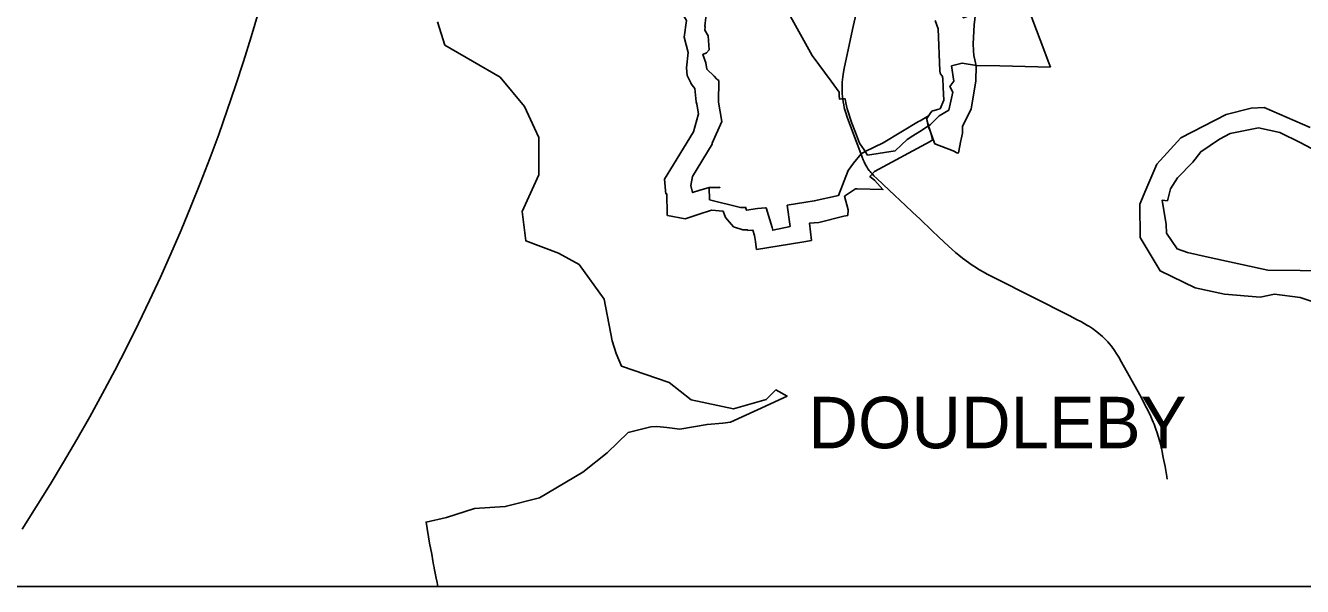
# Model space of a CAD drawing. Extents: x -759276 to -751881, y -1176141 to -1171097.
# Drawn here: x -757836 to -754995, y -1176141 to -1174894 of the extents above; entities that cross this region are included whole.
import ezdxf

# ---------------------------------------------------------------- set-up
doc = ezdxf.new("R2010")
doc.units = 0
for name, color, linetype in [('A_HRU', 7, 'Continuous'), ('A_OBCE', 7, 'Continuous'), ('A_SILNICE', 7, 'Continuous'), ('A_USES', 7, 'Continuous'), ('AA_vyrezy', 7, 'Continuous')]:
    doc.layers.add(name, color=color, linetype=linetype)

msp = doc.modelspace()

# ---------------------------------------------------------------- linework, layer by layer
at = {"layer": 'A_HRU'}
for points in [[(-759275.6, -1176140.6), (-759275.6, -1171097.2), (-751880.9, -1171097.2), (-751880.9, -1176140.6)], [(-751880.9, -1172828.3), (-753894.3, -1172828.3), (-753894.3, -1171097.2), (-759275.6, -1171097.2), (-759275.6, -1176140.6), (-753894.3, -1176140.6), (-753894.3, -1174884.8), (-751880.9, -1174884.8)]]:
    msp.add_lwpolyline(points, close=True, dxfattribs=at)
at = {"layer": 'A_OBCE'}
for p, q in [((-756085.5, -1174960.4), (-756144.8, -1174853.9)), ((-756919.6, -1174885.6), (-756903.2, -1174937.1)), ((-756903.2, -1174937.1), (-756780.2, -1175008.1)), ((-755667.9, -1174983.4), (-755555.2, -1174986)), ((-755556.7, -1174982.2), (-755555.2, -1174986)), ((-756780.2, -1175008.1), (-756726, -1175073.4)), ((-755781.7, -1175081.8), (-755772.9, -1175041.9)), ((-755772.9, -1175041.9), (-755781.7, -1175081.8)), ((-756014.6, -1175056.5), (-756020.6, -1175056.9)), ((-755802.9, -1175094.6), (-755817.8, -1175108.9)), ((-755781.7, -1175081.8), (-755802.9, -1175094.6)), ((-756693.9, -1175142.4), (-756703.6, -1175121.8)), ((-755989.3, -1175131.2), (-755997.3, -1175110.6)), ((-755989.3, -1175131.2), (-755980, -1175155.2)), ((-755825.3, -1175116.2), (-755826.5, -1175116.9)), ((-756694.1, -1175225.4), (-756693.9, -1175142.4)), ((-755980, -1175155.2), (-755970.2, -1175170.3)), ((-755874.6, -1175147.3), (-755901.1, -1175171.9)), ((-755861.7, -1175139.2), (-755874.6, -1175147.3)), ((-755962.6, -1175182.1), (-755967.9, -1175173.9)), ((-755901.1, -1175171.9), (-755962.6, -1175182.1)), ((-756548.7, -1175502.1), (-756530.6, -1175594.2)), ((-756530.6, -1175594.2), (-756521.6, -1175622.6)), ((-756188.2, -1175724.7), (-756260.6, -1175746)), ((-756166.5, -1175703.8), (-756188.2, -1175724.7)), ((-756267.7, -1175775.6), (-756207, -1175747.8)), ((-756284.1, -1175777.3), (-756319.6, -1175780.2)), ((-756284.1, -1175777.3), (-756267.7, -1175775.6)), ((-756541.7, -1175843.4), (-756495.4, -1175798)), ((-756495.4, -1175798), (-756541.7, -1175843.4)), ((-756541.7, -1175843.4), (-756595.6, -1175886.8)), ((-756595.6, -1175886.8), (-756692.4, -1175943.3)), ((-756692.4, -1175943.3), (-756768.6, -1175962.9)), ((-756944.6, -1175997.5), (-756936.9, -1176044.7)), ((-756936.9, -1176044.7), (-756932.2, -1176068.8)), ((-756926.5, -1176100.1), (-756922.1, -1176121.9)), ((-756922.1, -1176121.9), (-756920, -1176131.7)), ((-756918.3, -1176140.6), (-756920, -1176131.7)), ((-756920, -1176131.7), (-756918.3, -1176140.6)), ((-756918.3, -1176140.6), (-754601.6, -1176140.6))]:
    msp.add_line(p, q, dxfattribs=at)
for points in [[(-759275.6, -1171919), (-759275.6, -1176140.6), (-756918.3, -1176140.6)], [(-755555.2, -1174986), (-755556.7, -1174982.2), (-755558.8, -1174976.6), (-755578.4, -1174925.4), (-755594.5, -1174882.4), (-755599.2, -1174869.9), (-755609.7, -1174845)], [(-756144.8, -1174853.9), (-756085.5, -1174960.4), (-756043.4, -1175017.2)], [(-755599.2, -1174869.9), (-755594.5, -1174882.4), (-755578.4, -1174925.4)], [(-756780.2, -1175008.1), (-756903.2, -1174937.1), (-756919.6, -1174885.6)], [(-755578.4, -1174925.4), (-755558.8, -1174976.6), (-755556.7, -1174982.2)], [(-756025.2, -1175049.4), (-756025.4, -1175041.5), (-756043.4, -1175017.2), (-756085.5, -1174960.4)], [(-755770.2, -1175017.4), (-755775.6, -1174983.5), (-755752, -1174977), (-755720, -1174982.3), (-755667.9, -1174983.4)], [(-755720, -1174982.3), (-755752, -1174977), (-755775.6, -1174983.5), (-755770.2, -1175017.4)], [(-755555.2, -1174986), (-755667.9, -1174983.4), (-755720, -1174982.3)], [(-756703.6, -1175121.8), (-756726, -1175073.4), (-756780.2, -1175008.1)], [(-756043.4, -1175017.2), (-756025.4, -1175041.5), (-756025.2, -1175049.4), (-756025, -1175057.1)], [(-755772.9, -1175041.9), (-755779.2, -1175029.3), (-755770.2, -1175017.4)], [(-755770.2, -1175017.4), (-755779.2, -1175029.3), (-755772.9, -1175041.9)], [(-756726, -1175073.4), (-756703.6, -1175121.8), (-756693.9, -1175142.4)], [(-756020.6, -1175056.9), (-756025, -1175057.1), (-756025.2, -1175049.4)], [(-756025, -1175057.1), (-756020.6, -1175056.9), (-756014.6, -1175056.5), (-756012.4, -1175056.4), (-756010.5, -1175065.4)], [(-756010.5, -1175065.4), (-756012.4, -1175056.4), (-756014.6, -1175056.5)], [(-756010.5, -1175065.4), (-756007.4, -1175079.1), (-755997.3, -1175110.6), (-755989.3, -1175131.2)], [(-755997.3, -1175110.6), (-756007.4, -1175079.1), (-756010.5, -1175065.4)], [(-755817.8, -1175108.9), (-755802.9, -1175094.6), (-755781.7, -1175081.8)], [(-755967.9, -1175173.9), (-755970.2, -1175170.3), (-755980, -1175155.2), (-755989.3, -1175131.2)], [(-755962.6, -1175182.1), (-755901.1, -1175171.9), (-755874.6, -1175147.3), (-755861.7, -1175139.2), (-755845.7, -1175129.1), (-755826.5, -1175116.9), (-755825.3, -1175116.2), (-755822.4, -1175113.4), (-755817.8, -1175108.9)], [(-755826.5, -1175116.9), (-755845.7, -1175129.1), (-755861.7, -1175139.2)], [(-755817.8, -1175108.9), (-755822.4, -1175113.4), (-755825.3, -1175116.2)], [(-756693.9, -1175142.4), (-756694.1, -1175225.4), (-756731.1, -1175307), (-756722.7, -1175372.6), (-756650.1, -1175399.8)], [(-755970.2, -1175170.3), (-755967.9, -1175173.9), (-755962.6, -1175182.1)], [(-756650.1, -1175399.8), (-756722.7, -1175372.6), (-756731.1, -1175307), (-756694.1, -1175225.4)], [(-756548.7, -1175502.1), (-756603.8, -1175425.2), (-756650.1, -1175399.8)], [(-756650.1, -1175399.8), (-756603.8, -1175425.2), (-756548.7, -1175502.1)], [(-756403.8, -1175687.1), (-756510, -1175651.2), (-756521.6, -1175622.6), (-756530.6, -1175594.2), (-756548.7, -1175502.1)], [(-756521.6, -1175622.6), (-756510, -1175651.2), (-756403.8, -1175687.1), (-756354.8, -1175726)], [(-756260.6, -1175746), (-756354.8, -1175726), (-756403.8, -1175687.1)], [(-756354.8, -1175726), (-756260.6, -1175746), (-756188.2, -1175724.7)], [(-756188.2, -1175724.7), (-756166.5, -1175703.8), (-756141.5, -1175717.5), (-756207, -1175747.8), (-756267.7, -1175775.6), (-756284.1, -1175777.3)], [(-756207, -1175747.8), (-756141.5, -1175717.5), (-756166.5, -1175703.8)], [(-756319.6, -1175780.2), (-756380.4, -1175790.9), (-756409.2, -1175787.6), (-756431.6, -1175785)], [(-756409.2, -1175787.6), (-756380.4, -1175790.9), (-756319.6, -1175780.2), (-756284.1, -1175777.3)], [(-756495.4, -1175798), (-756444.5, -1175786), (-756431.6, -1175785), (-756409.2, -1175787.6)], [(-756431.6, -1175785), (-756444.5, -1175786), (-756495.4, -1175798)], [(-756692.4, -1175943.3), (-756595.6, -1175886.8), (-756541.7, -1175843.4)], [(-756927, -1176098.3), (-756928, -1176092.5), (-756929.4, -1176083.8), (-756932.2, -1176068.8), (-756936.9, -1176044.7), (-756944.6, -1175997.5), (-756899.2, -1175987.1), (-756837.2, -1175967), (-756768.6, -1175962.9), (-756692.4, -1175943.3)], [(-756768.6, -1175962.9), (-756837.2, -1175967), (-756899.2, -1175987.1), (-756944.6, -1175997.5)], [(-756932.2, -1176068.8), (-756929.4, -1176083.8), (-756928, -1176092.5)], [(-756928, -1176092.5), (-756927, -1176098.3), (-756926.5, -1176100.1)], [(-756920, -1176131.7), (-756922.1, -1176121.9), (-756926.5, -1176100.1), (-756927, -1176098.3)]]:
    msp.add_lwpolyline(points, dxfattribs=at)
at = {"layer": 'A_SILNICE'}
for points in [[(-757317.7, -1174864.2), (-757333.9, -1174919), (-757350.9, -1174973.5), (-757368.6, -1175027.9), (-757387.1, -1175081.9), (-757406.2, -1175135.8), (-757426.1, -1175189.3), (-757446.7, -1175242.6), (-757468, -1175295.7), (-757490, -1175348.4), (-757512.6, -1175400.9), (-757536, -1175453), (-757560.1, -1175504.8), (-757584.9, -1175556.3), (-757610.9, -1175608.6), (-757637.6, -1175660.5), (-757665, -1175712), (-757693.1, -1175763.2), (-757721.9, -1175813.9), (-757751.3, -1175864.3), (-757781.5, -1175914.3), (-757812.3, -1175963.8), (-757843.8, -1176013)], [(-755295.7, -1175901.8), (-755296.7, -1175895.9), (-755300.2, -1175873.8), (-755304.3, -1175853.7), (-755307.6, -1175837.1), (-755309.8, -1175827.8), (-755312.1, -1175819.1), (-755315, -1175808.6), (-755316.3, -1175804.2), (-755318, -1175799.1), (-755320.8, -1175791.2), (-755324.7, -1175780), (-755326.7, -1175775.1), (-755329, -1175770), (-755332.3, -1175762.6), (-755335.9, -1175754.7), (-755341.5, -1175743.4), (-755356.8, -1175714.9), (-755397, -1175642.1), (-755403.3, -1175631.1), (-755409.2, -1175621.7), (-755413.1, -1175616), (-755419.8, -1175606.7), (-755424.7, -1175600.6), (-755427.9, -1175597), (-755431.2, -1175593.4), (-755436.4, -1175588.2), (-755439.6, -1175585.2), (-755444.1, -1175581.2), (-755447.9, -1175577.9), (-755452.1, -1175574.6), (-755462.1, -1175567.5), (-755468.6, -1175562.9), (-755474.4, -1175559.4), (-755480.4, -1175555.8), (-755486.6, -1175552.5), (-755497.1, -1175546.8), (-755512.5, -1175538.9), (-755678.7, -1175455.6), (-755696.3, -1175446.5), (-755705.3, -1175441.4), (-755714.5, -1175436.1), (-755722.4, -1175431), (-755729.9, -1175426.1), (-755751, -1175410.9), (-755759.1, -1175404.4), (-755766.5, -1175398.2), (-755782.3, -1175384.1), (-755804, -1175363.8), (-755819.3, -1175349), (-755845.4, -1175324.3), (-755862.5, -1175308.4), (-755878.1, -1175293.5), (-755914.5, -1175259.3), (-755941.4, -1175234), (-755948.1, -1175227.7), (-755951.7, -1175224), (-755955.1, -1175220.2), (-755956.7, -1175218.4), (-755958.6, -1175216.1), (-755961.6, -1175212), (-755964.2, -1175207.8), (-755966.6, -1175203.6), (-755970.2, -1175196.7), (-755972.4, -1175191.9), (-755974.5, -1175186.4), (-755977.7, -1175178.1), (-755993.7, -1175135.5), (-756007.8, -1175097.2), (-756010.9, -1175087.7), (-756012.7, -1175081.3), (-756014.1, -1175076), (-756015.5, -1175069.8), (-756016.7, -1175063.3), (-756017.5, -1175057.4), (-756018.2, -1175051.2), (-756018.6, -1175045.6), (-756019, -1175039.8), (-756019.1, -1175031.4), (-756018.6, -1175019.7), (-756017.5, -1175007.7), (-756015.9, -1174997), (-756014.4, -1174989.1), (-756005, -1174943.9), (-755994.2, -1174896.1), (-755987.8, -1174867)]]:
    msp.add_lwpolyline(points, dxfattribs=at)
at = {"layer": 'A_USES'}
for p, q in [((-755800.5, -1174999.8), (-755800.1, -1175000.7)), ((-755731.9, -1175078.6), (-755721.7, -1175017.1)), ((-755831.2, -1175099.4), (-755827, -1175094.1)), ((-755829.5, -1175106.2), (-755831.2, -1175099.4)), ((-755826, -1175093.6), (-755830.5, -1175100.2)), ((-755830.5, -1175100.2), (-755829.5, -1175106.2)), ((-755823.3, -1175089.4), (-755826, -1175093.6)), ((-755822.7, -1175129.8), (-755816.2, -1175146.7)), ((-755754, -1175146.1), (-755751.4, -1175132.7)), ((-756414, -1175235.4), (-756411.5, -1175268.3)), ((-756099.4, -1175286.1), (-756141.5, -1175293.2)), ((-756408.2, -1175312.1), (-756408, -1175314.6)), ((-756408, -1175314.6), (-756407.2, -1175316)), ((-756209.4, -1175391.3), (-756108.6, -1175375.2)), ((-756108.6, -1175375.2), (-756087.2, -1175371.8))]:
    msp.add_line(p, q, dxfattribs=at)
for points in [[(-755727.5, -1174934.6), (-755725.3, -1174892), (-755722, -1174866.9), (-755749.5, -1174876.3), (-755760.7, -1174830.8), (-755766, -1174805.8), (-755750.7, -1174799.5)], [(-756371.8, -1174871.2), (-756365.2, -1174882.7), (-756370.3, -1174919.2)], [(-756323.8, -1174896.4), (-756324.6, -1174895.3), (-756322, -1174876.1), (-756320.1, -1174862.4), (-756319.8, -1174859.7)], [(-756321, -1174954.5), (-756315.2, -1174948), (-756317, -1174916.6), (-756324.8, -1174903.7), (-756323.8, -1174896.4)], [(-755812.2, -1174882.8), (-755805.6, -1174900.8), (-755801.3, -1174994), (-755800.5, -1174999.8)], [(-756370.3, -1174919.2), (-756361.9, -1174953.7), (-756365.5, -1174987.6), (-756363.7, -1175004.4)], [(-756322.1, -1174976.4), (-756329.2, -1174958), (-756321, -1174954.5)], [(-755725.5, -1174962.7), (-755725.6, -1174962.1), (-755727.6, -1174935.3), (-755727.5, -1174934.6)], [(-756303.8, -1175006), (-756320.2, -1174990.5), (-756322.1, -1174976.4)], [(-755721.9, -1174976.2), (-755725.5, -1174963), (-755725.5, -1174962.7)], [(-755721.7, -1175017.1), (-755720.7, -1174982.8), (-755721.9, -1174976.2)], [(-756363.7, -1175004.4), (-756355.6, -1175020.7), (-756355.7, -1175021.4)], [(-756307.9, -1175157.2), (-756308.2, -1175155.2), (-756286.7, -1175106.7), (-756294.2, -1175063.9), (-756293.3, -1175016), (-756294.6, -1175014.8)], [(-756294.6, -1175014.8), (-756298.6, -1175011.8), (-756303.8, -1175006)], [(-755795.6, -1175009.3), (-755795.1, -1175010.3), (-755794.2, -1175031.7), (-755792.6, -1175059.3), (-755800.9, -1175078.8), (-755806.5, -1175080.3)], [(-755800.1, -1175000.7), (-755795.7, -1175006.9), (-755795.6, -1175009.3)], [(-756355.7, -1175021.4), (-756352.8, -1175026.4), (-756346.6, -1175033.3), (-756343.4, -1175063.4), (-756342.6, -1175068.4), (-756338.2, -1175089.6), (-756349.9, -1175130.2), (-756394.4, -1175202.9), (-756414, -1175235.4)], [(-755827, -1175094.1), (-755845.6, -1175105.2), (-755849.2, -1175107.3), (-755928, -1175154.2), (-755967.9, -1175173.9), (-755968, -1175173.9), (-755976.9, -1175178.6), (-755993.3, -1175199.6)], [(-755806.5, -1175080.3), (-755819.1, -1175084.3), (-755823.3, -1175089.4)], [(-755751.4, -1175132.7), (-755751.4, -1175117.4), (-755734.5, -1175085.2)], [(-755734.5, -1175085.2), (-755732, -1175079), (-755731.9, -1175078.6)], [(-754977.5, -1175120.2), (-755079.8, -1175075.8), (-755108.5, -1175077.2), (-755164.5, -1175091.2), (-755265, -1175143.2), (-755318.9, -1175202.1), (-755343.1, -1175258.9), (-755356.5, -1175291), (-755356, -1175365.2), (-755311.2, -1175439.1), (-755233.6, -1175476.9), (-755168.1, -1175490.5), (-755088.6, -1175497.4), (-755056.6, -1175490.9), (-755000.1, -1175498), (-754879.2, -1175538.2)], [(-755829.5, -1175106.2), (-755826.3, -1175118.6), (-755822.7, -1175129.8)], [(-755822.7, -1175129.8), (-755827.4, -1175117.6), (-755829.5, -1175106.2)], [(-755818.2, -1175148), (-755819.9, -1175138.6), (-755822.7, -1175129.8)], [(-754918.8, -1175439.5), (-754999.8, -1175438.3), (-755071.8, -1175437.1), (-755204.8, -1175408.2), (-755250.6, -1175398.3), (-755273.6, -1175390.1), (-755297.2, -1175355.4), (-755298, -1175336.1), (-755306.7, -1175281.7), (-755295, -1175283.1), (-755288.1, -1175256.9), (-755272.4, -1175232.5), (-755238.5, -1175197.7), (-755220.9, -1175174.4), (-755179.2, -1175146.4), (-755155.5, -1175133.5), (-755092.2, -1175121.3), (-755045, -1175131.2), (-754999.7, -1175154), (-754974.4, -1175166.8)], [(-756290.9, -1175253), (-756314.9, -1175253.7), (-756337.5, -1175260.3), (-756351.9, -1175265), (-756355.5, -1175249.4), (-756351.7, -1175229), (-756307.9, -1175157.2)], [(-755946.4, -1175238.5), (-755954.7, -1175231.5), (-755957.1, -1175229.6), (-755947.1, -1175218.4), (-755823.2, -1175151.1), (-755818.2, -1175148)], [(-755816.2, -1175146.7), (-755812.4, -1175156.8), (-755771.6, -1175172.4), (-755762, -1175177.1)], [(-755762, -1175177.1), (-755760.3, -1175176.7), (-755754.6, -1175149.2), (-755754, -1175146.1)], [(-756005.7, -1175215.7), (-756027.1, -1175271.5), (-756081.1, -1175283.4), (-756099.4, -1175286.1)], [(-755993.3, -1175199.6), (-755993.4, -1175199.7), (-756005.6, -1175215.6), (-756005.7, -1175215.7)], [(-755985.4, -1175257), (-755928.2, -1175258.3), (-755946.4, -1175238.5)], [(-756411.5, -1175268.3), (-756409.2, -1175267.5), (-756408.2, -1175312.1)], [(-756232.6, -1175298.1), (-756245, -1175297.8), (-756314, -1175280.9), (-756315.2, -1175253.8), (-756290.9, -1175253.4), (-756290.9, -1175253)], [(-756087.2, -1175371.8), (-756091.3, -1175332.9), (-756070.6, -1175331.2), (-756015, -1175317.3), (-756006.6, -1175315.6), (-756005.3, -1175303.7), (-756013.4, -1175273), (-755988.9, -1175256.9), (-755987.7, -1175257)], [(-755987.7, -1175257), (-755987.8, -1175256.5), (-755985.4, -1175257)], [(-756189.4, -1175298.9), (-756207.2, -1175300.3), (-756232, -1175304.2), (-756232.9, -1175299.7), (-756232.6, -1175298.1)], [(-756174.4, -1175342.7), (-756174.6, -1175342.7), (-756188.1, -1175298.9), (-756189.4, -1175298.9)], [(-756141.5, -1175293.2), (-756134.9, -1175340.2), (-756173.2, -1175348.6), (-756174.4, -1175342.7)], [(-756407.2, -1175316), (-756368.3, -1175323.1), (-756368.2, -1175323.2)], [(-756368.2, -1175323.2), (-756337.3, -1175312.8), (-756309.6, -1175304.4), (-756283.9, -1175306.6), (-756278.4, -1175320.2), (-756260.5, -1175341.3), (-756239.6, -1175347.9)], [(-756239.6, -1175347.9), (-756229.4, -1175348.1), (-756229.2, -1175349.3)], [(-756229.2, -1175349.3), (-756217.7, -1175348.3), (-756213.7, -1175360.6), (-756211.6, -1175373.7), (-756210.3, -1175386.4), (-756209.4, -1175391.3)]]:
    msp.add_lwpolyline(points, dxfattribs=at)

# ---------------------------------------------------------------- texts
at = {"layer": 'AA_vyrezy'}
msp.add_text('DOUDLEBY', height=114.37, dxfattribs=at).set_placement((-756094.1, -1175833.4))

doc.saveas('drawing.dxf')
